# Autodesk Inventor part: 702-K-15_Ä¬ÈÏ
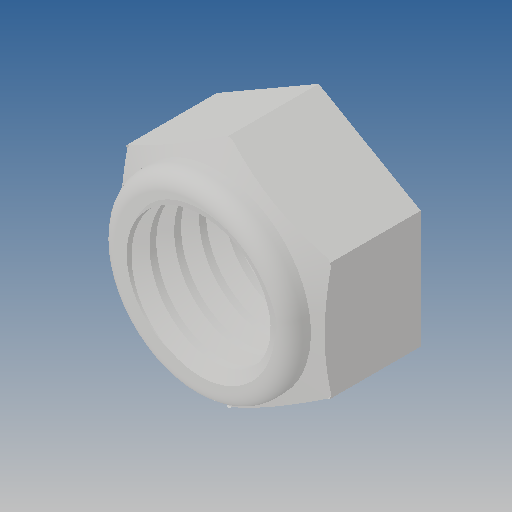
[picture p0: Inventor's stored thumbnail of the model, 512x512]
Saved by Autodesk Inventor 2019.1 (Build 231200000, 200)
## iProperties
Created: 2010-06
Part Number: 702-K-15_Ä¬ÈÏ
Material: Ogólny
Document SubType Name: Modeling
Designer: CADENGINEERING4
Density: 1 g/cm^3
Appearance: Domyślna
Author: CADENGINEERING4
Revision Number: ÈÎºÎ
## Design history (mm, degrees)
feature "NONE"
node "Bryła1"
